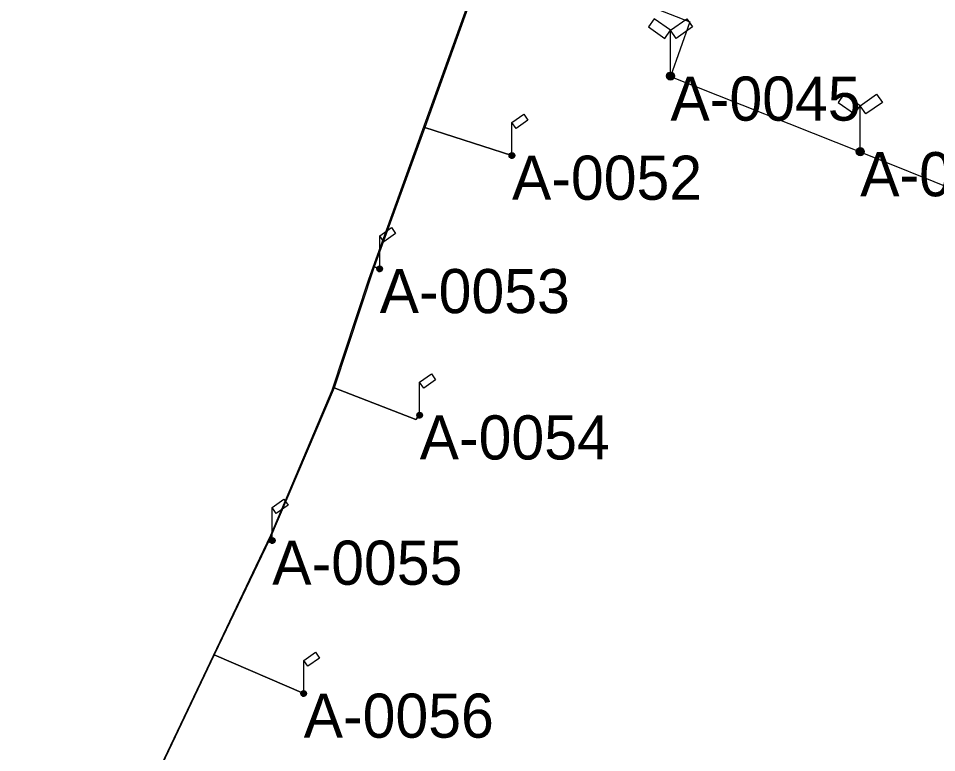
# Model space of a CAD drawing. Extents: x -729889 to -691139, y -995431 to -974354.
# Drawn here: x -725634.9 to -725572.5, y -978262.6 to -978212.7 of the extents above; entities that cross this region are included whole.
import ezdxf

# ---------------------------------------------------------------- set-up
doc = ezdxf.new("R2010")
doc.units = 0
for name, color, linetype in [('Atributy', 7, 'Continuous'), ('Kabelové vedení VO', 7, 'Continuous'), ('Světelný bod na stožáru s více svítidly', 7, 'Continuous'), ('Světelný bod na stožáru sadovém', 7, 'Continuous')]:
    doc.layers.add(name, color=color, linetype=linetype)

# ---------------------------------------------------------------- blocks, each defined once
blk = doc.blocks.new('6.563')
at = {"layer": 'Světelný bod na stožáru s více svítidly'}
blk.add_lwpolyline([(0.007, 3.135), (-1.104, 3.914), (-1.49, 3.359), (-0.386, 2.58)], close=True, dxfattribs=at)
for points in [[(0.007, 0.291), (0.007, 3.135), (1.111, 3.914), (1.503, 3.359), (0.393, 2.58), (0.007, 3.135)], [(0.278, 0.02), (0.23, -0.115), (0.102, -0.223), (-0.047, -0.23), (-0.169, -0.169), (-0.244, -0.041), (-0.237, 0.115), (-0.149, 0.23), (-0.027, 0.278), (0.122, 0.244), (0.223, 0.135), (0.251, 0.014), (0.196, -0.115), (0.074, -0.203), (-0.054, -0.203), (-0.163, -0.142), (-0.223, -0.014), (-0.203, 0.122), (-0.129, 0.21), (-0.007, 0.251), (0.129, 0.21), (0.203, 0.115), (0.223, 0.007), (0.169, -0.115), (0.054, -0.183), (-0.047, -0.176), (-0.149, -0.108), (-0.203, 0.007), (-0.176, 0.115), (-0.108, 0.196), (0.014, 0.223), (0.122, 0.183), (0.183, 0.102), (0.19, -0.007), (0.135, -0.108), (0.041, -0.156), (-0.054, -0.149), (-0.142, -0.081), (-0.176, 0.02), (-0.149, 0.108), (-0.081, 0.176), (0.027, 0.196), (0.108, 0.156), (0.163, 0.081), (0.163, -0.014), (0.108, -0.095), (0.034, -0.129), (-0.054, -0.122), (-0.129, -0.054), (-0.149, 0.027), (-0.122, 0.102), (-0.054, 0.163), (0.034, 0.169), (0.095, 0.135), (0.135, 0.068), (0.135, -0.02), (0.088, -0.081), (0.027, -0.108), (-0.054, -0.088), (-0.108, -0.034), (-0.122, 0.027), (-0.095, 0.095), (-0.034, 0.142), (0.034, 0.142), (0.081, 0.108), (0.115, 0.047), (0.108, -0.02), (0.068, -0.061), (0.014, -0.081), (-0.047, -0.061), (-0.088, -0.02), (-0.095, 0.034), (-0.074, 0.088), (-0.02, 0.115), (0.027, 0.115), (0.068, 0.088), (0.088, 0.041), (0.081, -0.014), (0.047, -0.041), (0.007, -0.054), (-0.041, -0.034), (-0.068, -0.007), (-0.068, 0.034), (-0.047, 0.074), (-0.014, 0.088), (0.02, 0.088), (0.054, 0.068), (0.061, 0.027), (0.054, 0), (0.034, -0.02), (0, -0.027), (-0.027, -0.014), (-0.041, 0.007), (-0.041, 0.034), (-0.027, 0.061), (-0.007, 0.068), (0.014, 0.061), (0.034, 0.047), (0.041, 0.027), (0.034, 0.007), (0.014, 0)], [(0.014, 0), (0, 0), (-0.014, 0.007), (-0.014, 0.02), (-0.014, 0.034), (-0.007, 0.041), (0, 0.041), (0.007, 0.034), (0.014, 0.027), (0.014, 0.027)], [(-0.007, 0), (0.007, 0), (0.02, 0.007), (0.027, 0.02), (0.02, 0.034), (0.014, 0.041), (0.007, 0.041), (0, 0.034), (-0.007, 0.027), (0, 0.027)]]:
    blk.add_lwpolyline(points, dxfattribs=at)
blk.add_circle((0.007, 0.02), 0.271, dxfattribs=at)
blk.add_circle((0.007, 0.02), 0.271, dxfattribs=at)
blk = doc.blocks.new('6.561')
at = {"layer": 'Světelný bod na stožáru sadovém'}
for points in [[(0, 0.195), (0, 2.24), (0.799, 2.8), (1.076, 2.401), (0.278, 1.841), (0, 2.24)], [(-0.195, 0), (-0.161, -0.097), (-0.073, -0.175), (0.039, -0.18), (0.127, -0.136), (0.18, -0.044), (0.17, 0.068), (0.112, 0.146), (0.019, 0.185), (-0.088, 0.161), (-0.161, 0.083), (-0.175, -0.005), (-0.141, -0.102), (-0.054, -0.161), (0.039, -0.161), (0.117, -0.117), (0.166, -0.024), (0.151, 0.073), (0.097, 0.136), (0.005, 0.166), (-0.088, 0.136), (-0.146, 0.068), (-0.156, -0.01), (-0.117, -0.097), (-0.039, -0.146), (0.039, -0.141), (0.112, -0.097), (0.146, -0.01), (0.131, 0.068), (0.078, 0.127), (-0.005, 0.146), (-0.083, 0.117), (-0.127, 0.058), (-0.136, -0.019), (-0.093, -0.093), (-0.029, -0.127), (0.039, -0.122), (0.102, -0.073), (0.127, 0), (0.112, 0.063), (0.063, 0.112), (-0.015, 0.127), (-0.078, 0.097), (-0.112, 0.049), (-0.112, -0.024), (-0.078, -0.083), (-0.024, -0.107), (0.044, -0.102), (0.093, -0.054), (0.107, 0.005), (0.093, 0.058), (0.044, 0.102), (-0.019, 0.107), (-0.068, 0.083), (-0.097, 0.034), (-0.093, -0.029), (-0.058, -0.073), (-0.015, -0.093), (0.044, -0.078), (0.083, -0.039), (0.093, 0.005), (0.073, 0.054), (0.029, 0.088), (-0.019, 0.088), (-0.058, 0.063), (-0.078, 0.019), (-0.073, -0.029), (-0.049, -0.058), (-0.005, -0.073), (0.039, -0.058), (0.068, -0.029), (0.073, 0.01), (0.054, 0.049), (0.019, 0.068), (-0.015, 0.068), (-0.044, 0.049), (-0.063, 0.01), (-0.054, -0.024), (-0.034, -0.044), (0, -0.054), (0.034, -0.044), (0.049, -0.019), (0.054, 0.01), (0.034, 0.039), (0.01, 0.054), (-0.015, 0.049), (-0.034, 0.034), (-0.044, 0.005), (-0.039, -0.015), (-0.019, -0.029), (0.005, -0.034), (0.024, -0.024), (0.034, -0.01), (0.034, 0.01), (0.019, 0.024), (0.005, 0.034), (-0.01, 0.029), (-0.019, 0.019), (-0.024, 0.005), (-0.019, -0.005), (-0.01, -0.015)], [(-0.01, -0.015), (0.005, -0.015), (0.01, -0.01), (0.015, 0), (0.015, 0.01), (0.01, 0.015), (0, 0.015), (-0.005, 0.01), (-0.005, 0.005), (-0.005, 0.005)]]:
    blk.add_lwpolyline(points, dxfattribs=at)
blk.add_circle((0, 0), 0.195, dxfattribs=at)

msp = doc.modelspace()

# ---------------------------------------------------------------- linework, layer by layer
at = {"layer": 'Kabelové vedení VO'}
for p, q in [((-725590.58, -978216.62), (-725577.67, -978221.76)), ((-725577.67, -978221.76), (-725563.43, -978227.46))]:
    msp.add_line(p, q, dxfattribs=at)
for points in [[(-725653.59, -978298.41), (-725653.89, -978296.91), (-725642.031, -978300.582), (-725639.78, -978295.19), (-725635.52, -978285.34), (-725628.12, -978269.58), (-725618.76, -978249.9), (-725617.76, -978247.811), (-725613.6, -978237.96), (-725611.09, -978230.42), (-725603.85, -978210.28), (-725597.63, -978193.21), (-725591.48, -978175.75), (-725590.09, -978171.42), (-725588.131, -978163.256), (-725586.85, -978155.84), (-725586.347, -978153.04), (-725580.56, -978153.76), (-725578.28, -978155.35), (-725576.83, -978156.04), (-725569.6, -978158.18), (-725569.52, -978157.83)], [(-725603.53, -978209.6), (-725603.388, -978209.393), (-725602.76, -978207.64), (-725589.26, -978212.9), (-725590.58, -978216.62)], [(-725603.53, -978209.6), (-725607.29, -978220.09), (-725601.36, -978222)], [(-725601.36, -978222), (-725607.29, -978220.09), (-725610.74, -978229.57), (-725610.36, -978229.71)], [(-725610.36, -978229.71), (-725610.74, -978229.57), (-725613.46, -978237.79), (-725607.9, -978239.96), (-725607.64, -978239.66)], [(-725607.64, -978239.66), (-725607.9, -978239.96), (-725613.46, -978237.79), (-725617.85, -978248.12), (-725617.67, -978248.18)], [(-725617.67, -978248.18), (-725617.85, -978248.12), (-725621.61, -978255.95), (-725615.53, -978258.58)], [(-725615.53, -978258.58), (-725621.61, -978255.95), (-725626.488, -978266.194), (-725626.18, -978266.38)]]:
    msp.add_lwpolyline(points, dxfattribs=at)

# ---------------------------------------------------------------- block references
at = {"layer": 'Světelný bod na stožáru s více svítidly'}
for name, p, xscale, yscale in [('6.563', (-725590.58, -978216.62), 1.0022624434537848, 1.0022624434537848), ('6.563', (-725577.67, -978221.76), 1.0022624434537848, 1.0022624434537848), ('6.561', (-725601.36, -978222), 1.001626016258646, 1.001626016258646), ('6.561', (-725610.36, -978229.71), 1.001626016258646, 1.001626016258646), ('6.561', (-725607.64, -978239.66), 1.001626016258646, 1.001626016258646), ('6.561', (-725617.67, -978248.18), 1.001626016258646, 1.001626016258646), ('6.561', (-725615.53, -978258.58), 1.001626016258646, 1.001626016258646)]:
    msp.add_blockref(name, p, dxfattribs=dict(at, xscale=xscale, yscale=yscale))

# ---------------------------------------------------------------- texts
at = {"layer": 'Atributy'}
for s, p in [('A-0045', (-725590.58, -978219.631)), ('A-0052', (-725601.36, -978225.011)), ('A-0046', (-725577.67, -978224.771)), ('A-0053', (-725610.36, -978232.721)), ('A-0054', (-725607.64, -978242.671)), ('A-0055', (-725617.67, -978251.191)), ('A-0056', (-725615.53, -978261.591))]:
    msp.add_text(s, height=3, dxfattribs=at).set_placement(p)

doc.saveas('drawing.dxf')
